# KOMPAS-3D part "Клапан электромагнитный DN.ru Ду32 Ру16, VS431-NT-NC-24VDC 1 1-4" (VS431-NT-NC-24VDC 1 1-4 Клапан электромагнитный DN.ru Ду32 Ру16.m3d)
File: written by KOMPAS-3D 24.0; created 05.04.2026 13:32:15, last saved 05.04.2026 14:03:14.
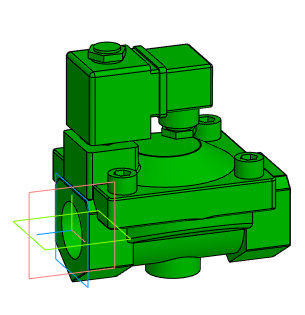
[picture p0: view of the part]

Document properties: Автор: artio; Полное имя файла: C:\Users\artio\OneDrive\Рабочий стол\Клапан электромагнитный DN.ru\VS431\VS431-NT-NC\VS431-NT-NC-24VDC\Ду32\VS431-NT-NC-24VDC 1 1-4 Клапан электромагнитный DN.ru Ду32 Ру16.m3d

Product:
- Body: Тело 1  | qty 1
    Масса: 3.709873
- Part/product: Клапан электромагнитный DN.ru Ду32 Ру16  | designation VS431-NT-NC-24VDC 1 1-4
    Масса: 1.701
    Раздел спецификации: Прочие изделия
    Примечание: D130-04750
    additional columns: ef56311e-7521-43dc-8291-0e6108b3d81d; artio; c; Шероховатость не задана; Да

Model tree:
1. Операция без истории:1

Expressions: VS431-NT-NC-24VDC 1 1-4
